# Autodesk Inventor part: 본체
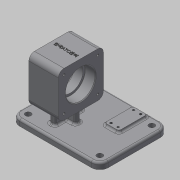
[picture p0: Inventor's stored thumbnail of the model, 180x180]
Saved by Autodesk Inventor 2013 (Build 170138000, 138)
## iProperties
Created: 2019-09
Part Number: 본체
Material: 일반
Document SubType Name: Modeling
Designer: mduedu
Density: 1 g/cm^3
Author: mduedu
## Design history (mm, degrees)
sketch "스케치1"
  geometry: L1 (42, -62)-(-84, -62); L2 (-84, -62)-(-84, 36); L3 (-84, 36)-(42, 36); L4 (42, 36)-(42, -62); 1 further point
  constraints: 8 end point, 2 parallel, 1 horizontal, 1 perpendicular
  dimensions: "d0" = 36 distance from line of L3 point (0, 0); "d1" = 98 distance of L1.end L2.end; "d2" = 42 distance from line of L4 point (0, 0); "d3" = 126 distance of L2.end L3.end
extrude "돌출1" new body sketch "스케치1" distance "d4" = 9; taper "d5" = 0 deg
sketch "스케치2"
  geometry: L1 (0, -62)-(0, 36) reference; L2 (27, -32)-(91, -32); L3 (91, -32)-(91, 32); L4 (91, 32)-(27, 32); L5 (27, 32)-(27, -32); L6 (27, -32)-(91, 32); L7 (91, -32)-(27, 32); 3 further points
  constraints: 12 end point, 3 midpoint, 2 parallel, 1 horizontal, 1 horizontal alignment, 1 perpendicular
  dimensions: "d87" = 64 distance of L4.end L3.end; "d88" = 64 distance of L3.end L2.end; "d89" = 59 distance from line of point (59, 0) L1
extrude "돌출2" join sketch "스케치2" stored distance "d8" = 42; taper "d9" = 0 deg
sketch "스케치3"
  geometry: L1 (-17, 4)-(17, 4); L2 (17, 4)-(17, -4); L3 (17, -4)-(-17, -4); L4 (-17, -4)-(-17, 4); L5 (-4, 20)-(4, 20); L6 (4, 20)-(4, -20); L7 (4, -20)-(-4, -20); L8 (-4, -20)-(-4, 20); 5 further points
  constraints: 16 end point, 4 midpoint, 4 parallel, 2 horizontal, 2 horizontal alignment, 2 perpendicular, 2 vertical alignment
  dimensions: "d10" = 8 distance of L5.start L5.end; "d12" = 8 distance of L1.end L2.end; "d13" = 34 distance of L2.end L3.end; "d14" = 40 distance of L5.end L6.end
extrude "돌출3" join sketch "스케치3" stored distance "d15" = 42; taper "d16" = 0 deg
sketch "스케치4"
  geometry: L1 (-32, 91)-(-32, 27) reference; L2 (32, 91)-(-32, 91) reference; L3 (32, 27)-(32, 91) reference; L4 (-32, 27)-(32, 27) reference; C1 r 21 at (0, 59); 3 further points
  constraints: 2 midpoint, 1 centre point, 1 horizontal alignment, 1 vertical alignment
  dimensions: "d17" = 42 diameter of C1
extrude "돌출4" cut sketch "스케치4" distance "d18" = 15; taper "d19" = 0 deg
hole "구멍1" diameter "d22" = 36; stored, may be unused: countersink angle "d26" = 90 deg, drill point angle "d28" = 118 deg; dims "d20" = 10, "d21" = 10, "d23" = 6, "d24" = 4, "d25" = 2, "d27" = 8
fillet "모깎기1" dims "d29" = 0.3
chamfer "모따기1" distance "d30" = 1; stored, may be unused: second distance "d31" = 2, angle "d32" = 45 deg
fillet "모깎기9" dims "d90" = 8
sketch "스케치11"
  geometry: L1 (-24, 27)-(24, 27) reference; L2 (32, 35)-(32, 83) reference; L3 (24, 91)-(-24, 91) reference; L4 (-32, 83)-(-32, 35) reference; C1 r 22 at (0, 59) reference; A1 r 8 centre (-24, 35) between (-32, 35) and (-24, 27) reference; A2 r 8 centre (24, 35) between (24, 27) and (32, 35) reference; A3 r 8 centre (24, 83) between (32, 83) and (24, 91) reference; A4 r 8 centre (-24, 83) between (-24, 91) and (-32, 83) reference; 5 further points
  constraints: 4 coincident
hole "구멍6" sketch "스케치11" at (-24, 83), (24, 83), (24, 35), (-24, 35) diameter "d91" = 3.242; stored, may be unused: countersink angle "d95" = 90 deg, drill point angle "d97" = 118 deg; dims "d92" = 8, "d93" = 4, "d94" = 2, "d96" = 10
fillet "모깎기2" dims "d44" = 12
sketch "스케치6"
  geometry: L1 (-42, 50)-(-42, -24) reference; L2 (-30, -36)-(72, -36) reference; L3 (84, -24)-(84, 50) reference; L4 (72, 62)-(-30, 62) reference; L5 (17, 4)-(17, -4) reference; L6 (17, -4)-(4, -4) reference; L7 (4, -4)-(4, -20) reference; L8 (4, -20)-(-4, -20) reference; L9 (-4, -20)-(-4, -4) reference; L10 (-4, -4)-(-17, -4) reference; L11 (-17, -4)-(-17, 4) reference; L12 (-17, 4)-(-4, 4) reference; L13 (-4, 4)-(-4, 20) reference; L14 (-4, 20)-(4, 20) reference; L15 (4, 20)-(4, 4) reference; L16 (4, 4)-(17, 4) reference; A1 r 12 centre (-30, 50) between (-30, 62) and (-42, 50) reference; A2 r 12 centre (-30, -24) between (-42, -24) and (-30, -36) reference; A3 r 12 centre (72, -24) between (72, -36) and (84, -24) reference; A4 r 12 centre (72, 50) between (84, 50) and (72, 62) reference; 5 further points
  constraints: 4 coincident
hole "구멍3" sketch "스케치6" at (-30, 50), (72, 50), (72, -24), (-30, -24) diameter "d45" = 8; stored, may be unused: countersink angle "d49" = 90 deg, drill point angle "d51" = 118 deg; dims "d46" = 8, "d47" = 4, "d48" = 2, "d50" = 10
sketch "스케치7"
  geometry: L1 (38, 57)-(58, 57); L2 (58, 57)-(58, 17); L3 (58, 17)-(38, 17); L4 (38, 17)-(38, 57); L5 (72, 62)-(-30, 62) reference; 3 further points
  constraints: 8 end point, 2 midpoint, 2 parallel, 1 horizontal, 1 perpendicular
  dimensions: "d52" = 48 horizontal distance of point (48, 57) point (0, 0); "d53" = 20 distance of L1.start L1.end; "d54" = 40 distance of L1.end L2.end; "d55" = 25 distance from line of point (38, 37) L5
extrude "돌출5" join sketch "스케치7" distance "d56" = 3; taper "d57" = 0 deg
fillet "모깎기3" dims "d58" = 3
fillet "모깎기4" dims "d59" = 3
fillet "모깎기5" dims "d60" = 3
fillet "모깎기6" dims "d61" = 3
fillet "모깎기7" dims "d62" = 3
fillet "모깎기8" dims "d63" = 3
sketch "스케치8"
  geometry: L1 (72, 62)-(58.317, 62) reference; L2 (84, -24)-(84, 50) reference; C1 r 1.5 at (43, 53); C2 r 1.5 at (53, 21); 1 further point
  constraints: 2 centre point, 1 equal radius
  dimensions: "d64" = 3 diameter of C1; "d65" = 9 distance from line of C1.centre L1; "d66" = 32 vertical distance of C2.centre C1.centre; "d67" = 10 horizontal distance of C2.centre C1.centre; "d68" = 31 distance from line of L2 C2.centre
hole "구멍4" sketch "스케치8" at (43, 53), (53, 21) diameter "d69" = 3; stored, may be unused: countersink angle "d73" = 90 deg, drill point angle "d75" = 118 deg; dims "d70" = 8, "d71" = 4, "d72" = 2, "d74" = 6
sketch "스케치9"
  geometry: C1 r 1.5 at (43, 53) reference; C2 r 1.5 at (53, 21) reference; 3 further points
  constraints: 2 horizontal alignment, 2 vertical alignment
hole "구멍5" sketch "스케치9" at (53, 53), (43, 21) diameter "d76" = 3.242; stored, may be unused: countersink angle "d80" = 90 deg, drill point angle "d82" = 118 deg; dims "d77" = 6, "d78" = 4, "d79" = 2, "d81" = 8
sketch "스케치10"
  geometry: 2 further points
  constraints: 1 coincident, 1 other
feature "엠보싱1" sketch "스케치10" dims "d0" = 36, "d1" = 98, "d2" = 42, "d3" = 126, "d12" = 8, "d13" = 34, "d85" = 0.5, "d86" = 0
node "솔리드1"
mirror "대칭1"
mirror "대칭2"
node "투영된 루프1"
node "투영된 루프2"
